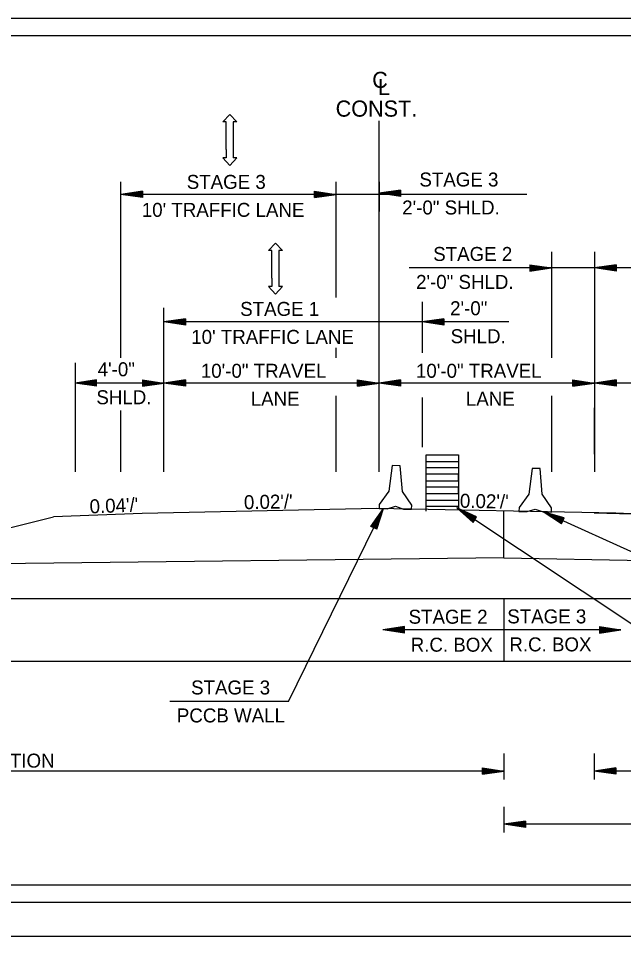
# Model space of a CAD drawing. Extents: x 1368648 to 1927880, y -1037443 to 380209.
# Drawn here: x 1372375 to 1372727, y 378686 to 379220 of the extents above; entities that cross this region are included whole.
import ezdxf

# ---------------------------------------------------------------- set-up
doc = ezdxf.new("R2010")
doc.units = 0
for name, color, linetype in [('CL Construction', 7, 'Continuous'), ('Default', 7, 'Continuous'), ('Dimensions', 7, 'Continuous'), ('Level 1', 7, 'Continuous'), ('R_Border', 7, 'Continuous'), ('R_Dimension', 7, 'Continuous'), ('R_Fin Surface', 7, 'Continuous'), ('R_MOT', 7, 'Continuous'), ('R_No Plot', 7, 'Continuous')]:
    doc.layers.add(name, color=color, linetype=linetype)

msp = doc.modelspace()

# ---------------------------------------------------------------- linework, layer by layer
at = {"layer": 'CL Construction'}
msp.add_line((1372584.51, 378956.16), (1372584.51, 379160.03), dxfattribs=at)
at = {"layer": 'Default'}
for p, q in [((1372611.88, 378965.96), (1372630.63, 378965.96)), ((1372611.88, 378933.35), (1372611.88, 378965.96)), ((1372630.63, 378965.96), (1372630.63, 378933.81)), ((1372611.88, 378962.21), (1372630.63, 378962.21)), ((1372611.88, 378958.46), (1372611.88, 378962.21)), ((1372630.63, 378958.46), (1372611.88, 378958.46)), ((1372630.63, 378954.71), (1372611.88, 378954.71)), ((1372630.63, 378950.96), (1372630.63, 378954.71)), ((1372611.88, 378950.96), (1372630.63, 378950.96)), ((1372630.63, 378947.21), (1372611.88, 378947.21)), ((1372611.88, 378943.46), (1372630.63, 378943.46)), ((1372630.63, 378943.46), (1372630.63, 378947.21)), ((1372611.88, 378939.71), (1372630.63, 378939.71)), ((1372611.88, 378935.96), (1372611.88, 378939.71)), ((1372630.63, 378935.96), (1372611.88, 378935.96)), ((1372656.97, 378906.24), (1372656.97, 378933.3)), ((1372656.97, 378906.24), (1372282.17, 378901.64)), ((1372656.97, 378906.24), (1372949.06, 378900.4)), ((1372205.32, 378882.43), (1372960.45, 378882.49)), ((1372656.97, 378882.47), (1372656.97, 378846.12)), ((1372141.41, 378846.12), (1373024.35, 378846.12))]:
    msp.add_line(p, q, dxfattribs=at)
at = {"layer": 'Dimensions'}
for p, q in [((1372499.82, 379159.39), (1372499.82, 379138.49)), ((1372526.35, 379084.63), (1372526.35, 379063.74))]:
    msp.add_line(p, q, dxfattribs=at)
for points in [[(1372495.76, 379143.37), (1372495.76, 379159.39), (1372493.73, 379159.39), (1372497.79, 379163.84), (1372501.85, 379159.39), (1372499.82, 379159.39)], [(1372495.76, 379143.37), (1372495.76, 379138.49), (1372493.73, 379138.49), (1372497.79, 379134.04), (1372501.85, 379138.49), (1372499.82, 379138.49)], [(1372522.28, 379068.61), (1372522.28, 379084.63), (1372520.25, 379084.63), (1372524.31, 379089.08), (1372528.38, 379084.63), (1372526.35, 379084.63)], [(1372522.28, 379068.61), (1372522.28, 379063.74), (1372520.25, 379063.74), (1372524.31, 379059.29), (1372528.38, 379063.74), (1372526.35, 379063.74)]]:
    msp.add_lwpolyline(points, dxfattribs=at)
at = {"layer": 'Level 1'}
for p, q in [((1372592.1, 378959.71), (1372590.24, 378944.82)), ((1372596.81, 378959.61), (1372592.1, 378959.71)), ((1372598.09, 378944.66), (1372596.81, 378959.61)), ((1372673.31, 378958.11), (1372671.45, 378943.23)), ((1372678.02, 378958.02), (1372673.31, 378958.11)), ((1372679.3, 378943.07), (1372678.02, 378958.02)), ((1372590.24, 378944.82), (1372584.59, 378937.07)), ((1372603.43, 378936.7), (1372598.09, 378944.66)), ((1372671.45, 378943.23), (1372665.8, 378935.48)), ((1372684.64, 378935.11), (1372679.3, 378943.07)), ((1372584.59, 378937.07), (1372584.51, 378934.72)), ((1372584.51, 378934.72), (1372589.22, 378934.63)), ((1372589.22, 378934.63), (1372593.97, 378936.1)), ((1372593.97, 378936.1), (1372598.65, 378934.44)), ((1372598.65, 378934.44), (1372603.36, 378934.35)), ((1372603.36, 378934.35), (1372603.43, 378936.7)), ((1372665.8, 378935.48), (1372665.73, 378933.13)), ((1372665.73, 378933.13), (1372670.44, 378933.03)), ((1372670.44, 378933.03), (1372675.18, 378934.51)), ((1372675.18, 378934.51), (1372679.86, 378932.85)), ((1372679.86, 378932.85), (1372684.57, 378932.76)), ((1372684.57, 378932.76), (1372684.64, 378935.11))]:
    msp.add_line(p, q, dxfattribs=at)
at = {"layer": 'R_Border'}
for p, q in [((1373388.3, 379219.61), (1371807.4, 379219.61)), ((1373388.3, 378705.96), (1371807.4, 378705.96))]:
    msp.add_line(p, q, dxfattribs=at)
at = {"layer": 'R_Dimension'}
for p, q in [((1372434.51, 379022.35), (1372434.51, 379124.6)), ((1372559.51, 379057.43), (1372559.51, 379124.6)), ((1372584.51, 379124.6), (1372584.51, 379107.42)), ((1372447.01, 379119.18), (1372434.51, 379117.31)), ((1372447.01, 379119.18), (1372447.01, 379115.43)), ((1372547.01, 379119.18), (1372559.51, 379117.31)), ((1372547.01, 379115.43), (1372547.01, 379119.18)), ((1372597.01, 379119.82), (1372584.51, 379117.95)), ((1372597.01, 379119.51), (1372586.6, 379117.95)), ((1372597.01, 379119.19), (1372588.75, 379117.95)), ((1372597.01, 379119.82), (1372597.01, 379116.07)), ((1372670.3, 379117.31), (1372434.51, 379117.31)), ((1372447.01, 379115.43), (1372434.51, 379117.31)), ((1372447.01, 379118.87), (1372436.6, 379117.31)), ((1372447.01, 379115.75), (1372436.6, 379117.31)), ((1372447.01, 379118.55), (1372438.75, 379117.31)), ((1372447.01, 379116.06), (1372438.75, 379117.31)), ((1372447.01, 379118.24), (1372440.83, 379117.31)), ((1372447.01, 379116.38), (1372440.83, 379117.31)), ((1372447.01, 379117.91), (1372442.95, 379117.31)), ((1372447.01, 379116.7), (1372442.95, 379117.31)), ((1372447.01, 379117.6), (1372445.04, 379117.31)), ((1372447.01, 379117.01), (1372445.04, 379117.31)), ((1372547.01, 379118.87), (1372557.43, 379117.31)), ((1372547.01, 379118.55), (1372555.28, 379117.31)), ((1372547.01, 379118.24), (1372553.19, 379117.31)), ((1372547.01, 379117.92), (1372551.08, 379117.31)), ((1372547.01, 379117.6), (1372548.99, 379117.31)), ((1372547.01, 379115.43), (1372559.51, 379117.31)), ((1372547.01, 379116.7), (1372551.08, 379117.31)), ((1372547.01, 379116.06), (1372555.28, 379117.31)), ((1372547.01, 379115.75), (1372557.43, 379117.31)), ((1372547.01, 379116.38), (1372553.19, 379117.31)), ((1372547.01, 379117.01), (1372548.99, 379117.31)), ((1372597.01, 379116.07), (1372584.51, 379117.95)), ((1372597.01, 379116.38), (1372586.6, 379117.95)), ((1372597.01, 379116.7), (1372588.75, 379117.95)), ((1372597.01, 379118.88), (1372590.83, 379117.95)), ((1372597.01, 379117.02), (1372590.83, 379117.95)), ((1372597.01, 379118.55), (1372592.95, 379117.95)), ((1372597.01, 379117.33), (1372592.95, 379117.95)), ((1372597.01, 379118.24), (1372595.04, 379117.95)), ((1372597.01, 379117.65), (1372595.04, 379117.95)), ((1372684.57, 379084), (1372684.57, 379022.35)), ((1372709.57, 379084), (1372709.57, 378956.16)), ((1372672.07, 379076.46), (1372684.57, 379074.59)), ((1372672.07, 379076.46), (1372672.07, 379072.71)), ((1372722.13, 379076.45), (1372709.63, 379074.58)), ((1372722.13, 379076.45), (1372722.13, 379072.7)), ((1372847.17, 379074.58), (1372601.97, 379074.58)), ((1372672.07, 379076.15), (1372682.48, 379074.59)), ((1372672.07, 379075.83), (1372680.33, 379074.59)), ((1372672.07, 379075.52), (1372678.25, 379074.59)), ((1372672.07, 379075.19), (1372676.13, 379074.59)), ((1372672.07, 379074.88), (1372674.05, 379074.59)), ((1372672.07, 379072.71), (1372684.57, 379074.59)), ((1372672.07, 379073.98), (1372676.13, 379074.59)), ((1372672.07, 379073.34), (1372680.33, 379074.59)), ((1372672.07, 379073.03), (1372682.48, 379074.59)), ((1372672.07, 379073.66), (1372678.25, 379074.59)), ((1372672.07, 379074.29), (1372674.05, 379074.59)), ((1372722.13, 379072.7), (1372709.63, 379074.58)), ((1372722.13, 379076.14), (1372711.72, 379074.58)), ((1372722.13, 379073.02), (1372711.72, 379074.58)), ((1372722.13, 379075.82), (1372713.87, 379074.58)), ((1372722.13, 379073.34), (1372713.87, 379074.58)), ((1372722.13, 379075.51), (1372715.95, 379074.58)), ((1372722.13, 379073.65), (1372715.95, 379074.58)), ((1372722.13, 379075.19), (1372718.07, 379074.58)), ((1372722.13, 379073.97), (1372718.07, 379074.58)), ((1372722.13, 379074.87), (1372720.15, 379074.58)), ((1372722.13, 379074.29), (1372720.15, 379074.58)), ((1372459.55, 379023.3), (1372459.52, 379051.47)), ((1372609.51, 379054.94), (1372609.51, 379025.27)), ((1372472.04, 379045.05), (1372459.54, 379043.18)), ((1372472.04, 379044.74), (1372461.63, 379043.18)), ((1372472.04, 379044.42), (1372463.78, 379043.18)), ((1372472.04, 379045.05), (1372472.04, 379041.3)), ((1372622.01, 379045.05), (1372609.51, 379043.18)), ((1372622.01, 379044.74), (1372611.6, 379043.18)), ((1372622.01, 379044.42), (1372613.75, 379043.18)), ((1372622.01, 379045.05), (1372622.01, 379041.3)), ((1372584.49, 379043.18), (1372459.54, 379043.18)), ((1372472.04, 379041.3), (1372459.54, 379043.18)), ((1372472.04, 379041.61), (1372461.63, 379043.18)), ((1372472.04, 379041.93), (1372463.78, 379043.18)), ((1372472.04, 379044.11), (1372465.86, 379043.18)), ((1372472.04, 379042.24), (1372465.86, 379043.18)), ((1372472.04, 379043.78), (1372467.98, 379043.18)), ((1372472.04, 379042.56), (1372467.98, 379043.18)), ((1372472.04, 379043.47), (1372470.06, 379043.18)), ((1372472.04, 379042.88), (1372470.06, 379043.18)), ((1372659.94, 379043.18), (1372584.51, 379043.18)), ((1372622.01, 379041.3), (1372609.51, 379043.18)), ((1372622.01, 379041.61), (1372611.6, 379043.18)), ((1372622.01, 379041.93), (1372613.75, 379043.18)), ((1372622.01, 379044.11), (1372615.83, 379043.18)), ((1372622.01, 379042.24), (1372615.83, 379043.18)), ((1372622.01, 379043.78), (1372617.95, 379043.18)), ((1372622.01, 379042.56), (1372617.95, 379043.18)), ((1372622.01, 379043.47), (1372620.04, 379043.18)), ((1372622.01, 379042.88), (1372620.04, 379043.18)), ((1372459.55, 378997.03), (1372459.55, 379023.3)), ((1372559.51, 379022.35), (1372559.51, 379028.18)), ((1372407.96, 379019.44), (1372407.96, 378966.59)), ((1372420.46, 379009.56), (1372407.96, 379007.69)), ((1372459.54, 379007.69), (1372407.96, 379007.69)), ((1372420.46, 379005.81), (1372407.96, 379007.69)), ((1372420.46, 379009.25), (1372410.05, 379007.69)), ((1372420.46, 379006.13), (1372410.05, 379007.69)), ((1372420.46, 379008.93), (1372412.2, 379007.69)), ((1372420.46, 379006.45), (1372412.2, 379007.69)), ((1372420.46, 379008.62), (1372414.28, 379007.69)), ((1372420.46, 379006.76), (1372414.28, 379007.69)), ((1372420.46, 379008.3), (1372416.4, 379007.69)), ((1372420.46, 379007.08), (1372416.4, 379007.69)), ((1372420.46, 379007.98), (1372418.49, 379007.69)), ((1372420.46, 379007.4), (1372418.49, 379007.69)), ((1372420.46, 379005.81), (1372420.46, 379009.56)), ((1372447.04, 379009.56), (1372459.54, 379007.69)), ((1372447.04, 379009.56), (1372447.04, 379005.81)), ((1372447.04, 379009.25), (1372457.45, 379007.69)), ((1372447.04, 379008.93), (1372455.3, 379007.69)), ((1372447.04, 379008.62), (1372453.22, 379007.69)), ((1372447.04, 379008.3), (1372451.1, 379007.69)), ((1372447.04, 379007.98), (1372449.01, 379007.69)), ((1372447.04, 379005.81), (1372459.54, 379007.69)), ((1372447.04, 379007.08), (1372451.1, 379007.69)), ((1372447.04, 379006.45), (1372455.3, 379007.69)), ((1372447.04, 379006.13), (1372457.45, 379007.69)), ((1372447.04, 379006.76), (1372453.22, 379007.69)), ((1372447.04, 379007.4), (1372449.01, 379007.69)), ((1372472.04, 379009.56), (1372459.54, 379007.69)), ((1372584.49, 379007.69), (1372459.54, 379007.69)), ((1372472.04, 379005.81), (1372459.54, 379007.69)), ((1372472.04, 379009.25), (1372461.63, 379007.69)), ((1372472.04, 379006.13), (1372461.63, 379007.69)), ((1372472.04, 379008.93), (1372463.78, 379007.69)), ((1372472.04, 379006.45), (1372463.78, 379007.69)), ((1372472.04, 379008.62), (1372465.86, 379007.69)), ((1372472.04, 379006.76), (1372465.86, 379007.69)), ((1372472.04, 379008.3), (1372467.98, 379007.69)), ((1372472.04, 379007.08), (1372467.98, 379007.69)), ((1372472.04, 379007.98), (1372470.06, 379007.69)), ((1372472.04, 379007.4), (1372470.06, 379007.69)), ((1372472.04, 379009.56), (1372472.04, 379005.81)), ((1372572.05, 379009.57), (1372584.55, 379007.7)), ((1372572.05, 379005.82), (1372572.05, 379009.57)), ((1372572.05, 379009.26), (1372582.46, 379007.7)), ((1372572.05, 379008.94), (1372580.31, 379007.7)), ((1372572.05, 379008.63), (1372578.23, 379007.7)), ((1372572.05, 379008.31), (1372576.11, 379007.7)), ((1372572.05, 379007.99), (1372574.02, 379007.7)), ((1372572.05, 379005.82), (1372584.55, 379007.7)), ((1372572.05, 379007.09), (1372576.11, 379007.7)), ((1372572.05, 379006.45), (1372580.31, 379007.7)), ((1372572.05, 379006.14), (1372582.46, 379007.7)), ((1372572.05, 379006.77), (1372578.23, 379007.7)), ((1372572.05, 379007.4), (1372574.02, 379007.7)), ((1372596.99, 379009.56), (1372584.49, 379007.69)), ((1372709.5, 379007.69), (1372584.49, 379007.69)), ((1372596.99, 379005.81), (1372584.49, 379007.69)), ((1372596.99, 379009.25), (1372586.58, 379007.69)), ((1372596.99, 379006.13), (1372586.58, 379007.69)), ((1372596.99, 379008.93), (1372588.73, 379007.69)), ((1372596.99, 379006.45), (1372588.73, 379007.69)), ((1372596.99, 379008.62), (1372590.81, 379007.69)), ((1372596.99, 379006.76), (1372590.81, 379007.69)), ((1372596.99, 379008.3), (1372592.93, 379007.69)), ((1372596.99, 379007.08), (1372592.93, 379007.69)), ((1372596.99, 379007.98), (1372595.01, 379007.69)), ((1372596.99, 379007.4), (1372595.01, 379007.69)), ((1372596.99, 379009.56), (1372596.99, 379005.81)), ((1372697, 379009.56), (1372709.5, 379007.69)), ((1372697, 379005.81), (1372697, 379009.56)), ((1372697, 379009.25), (1372707.41, 379007.69)), ((1372697, 379008.93), (1372705.26, 379007.69)), ((1372697, 379008.62), (1372703.18, 379007.69)), ((1372697, 379008.3), (1372701.06, 379007.69)), ((1372697, 379007.98), (1372698.98, 379007.69)), ((1372697, 379005.81), (1372709.5, 379007.69)), ((1372697, 379007.08), (1372701.06, 379007.69)), ((1372697, 379006.45), (1372705.26, 379007.69)), ((1372697, 379006.13), (1372707.41, 379007.69)), ((1372697, 379006.76), (1372703.18, 379007.69)), ((1372697, 379007.4), (1372698.98, 379007.69)), ((1372722.13, 379009.55), (1372709.63, 379007.68)), ((1372722.13, 379005.8), (1372709.63, 379007.68)), ((1372924.68, 379007.68), (1372709.63, 379007.68)), ((1372722.13, 379009.24), (1372711.72, 379007.68)), ((1372722.13, 379006.12), (1372711.72, 379007.68)), ((1372722.13, 379008.92), (1372713.87, 379007.68)), ((1372722.13, 379006.43), (1372713.87, 379007.68)), ((1372722.13, 379008.61), (1372715.95, 379007.68)), ((1372722.13, 379006.75), (1372715.95, 379007.68)), ((1372722.13, 379008.28), (1372718.07, 379007.68)), ((1372722.13, 379007.07), (1372718.07, 379007.68)), ((1372722.13, 379007.97), (1372720.15, 379007.68)), ((1372722.13, 379007.38), (1372720.15, 379007.68)), ((1372722.13, 379009.55), (1372722.13, 379005.8)), ((1372459.55, 378975.88), (1372459.53, 378997.03)), ((1372559.51, 378956.16), (1372559.51, 379000.23)), ((1372609.51, 378999.26), (1372609.51, 378970.38)), ((1372684.57, 379000.23), (1372684.57, 378956.16)), ((1372434.51, 378956.16), (1372434.51, 378991.71)), ((1372709.57, 378966.34), (1372709.57, 378993.21)), ((1372459.55, 378956.16), (1372459.55, 378975.88)), ((1372407.96, 378966.59), (1372407.96, 378956.16)), ((1372531.93, 378822.67), (1372586.95, 378934.83)), ((1372579.76, 378924.44), (1372586.97, 378934.82)), ((1372580.04, 378924.3), (1372586.05, 378932.95)), ((1372582.85, 378922.92), (1372586.05, 378932.95)), ((1372583.13, 378922.78), (1372586.97, 378934.82)), ((1372798.39, 378822.67), (1372629.73, 378935.27)), ((1372639.08, 378926.77), (1372629.73, 378935.27)), ((1372641.16, 378929.89), (1372629.73, 378935.27)), ((1372639.25, 378927.03), (1372631.46, 378934.11)), ((1372640.99, 378929.63), (1372631.46, 378934.11)), ((1372640.81, 378929.37), (1372633.25, 378932.92)), ((1372639.43, 378927.3), (1372633.25, 378932.92)), ((1372922.45, 378822.67), (1372679.86, 378932.85)), ((1372690.47, 378925.97), (1372679.86, 378932.85)), ((1372692.02, 378929.39), (1372679.86, 378932.85)), ((1372580.33, 378924.16), (1372585.1, 378931.02)), ((1372580.61, 378924.03), (1372584.18, 378929.16)), ((1372580.9, 378923.88), (1372583.24, 378927.26)), ((1372581.99, 378923.35), (1372583.24, 378927.26)), ((1372582.28, 378923.2), (1372584.18, 378929.16)), ((1372582.56, 378923.06), (1372585.1, 378931.02)), ((1372639.61, 378927.56), (1372634.98, 378931.77)), ((1372640.64, 378929.11), (1372634.98, 378931.77)), ((1372640.46, 378928.84), (1372636.74, 378930.59)), ((1372639.79, 378927.83), (1372636.74, 378930.59)), ((1372640.29, 378928.58), (1372638.48, 378929.43)), ((1372639.96, 378928.09), (1372638.48, 378929.43)), ((1372639.08, 378926.77), (1372641.16, 378929.89)), ((1372690.59, 378926.26), (1372681.76, 378931.99)), ((1372691.89, 378929.1), (1372681.76, 378931.99)), ((1372691.76, 378928.81), (1372683.72, 378931.1)), ((1372690.73, 378926.55), (1372683.72, 378931.1)), ((1372690.86, 378926.83), (1372685.61, 378930.24)), ((1372691.63, 378928.53), (1372685.61, 378930.24)), ((1372691.49, 378928.24), (1372687.54, 378929.36)), ((1372690.99, 378927.13), (1372687.54, 378929.36)), ((1372691.36, 378927.95), (1372689.44, 378928.5)), ((1372691.12, 378927.41), (1372689.44, 378928.5)), ((1372690.47, 378925.97), (1372692.02, 378929.39)), ((1372583.13, 378922.78), (1372579.76, 378924.44)), ((1372581.18, 378923.74), (1372582.32, 378925.38)), ((1372581.71, 378923.48), (1372582.32, 378925.38)), ((1372599.16, 378866.17), (1372586.66, 378864.3)), ((1372724.92, 378864.3), (1372586.66, 378864.3)), ((1372599.16, 378862.42), (1372586.66, 378864.3)), ((1372599.16, 378865.86), (1372588.74, 378864.3)), ((1372599.16, 378862.73), (1372588.74, 378864.3)), ((1372599.16, 378865.54), (1372590.89, 378864.3)), ((1372599.16, 378863.05), (1372590.89, 378864.3)), ((1372599.16, 378865.23), (1372592.98, 378864.3)), ((1372599.16, 378863.37), (1372592.98, 378864.3)), ((1372599.16, 378864.91), (1372595.09, 378864.3)), ((1372599.16, 378863.69), (1372595.09, 378864.3)), ((1372599.16, 378864.59), (1372597.18, 378864.3)), ((1372599.16, 378864), (1372597.18, 378864.3)), ((1372599.16, 378862.42), (1372599.16, 378866.17)), ((1372712.42, 378866.17), (1372724.92, 378864.3)), ((1372712.42, 378866.17), (1372712.42, 378862.42)), ((1372712.42, 378865.86), (1372722.83, 378864.3)), ((1372712.42, 378865.54), (1372720.68, 378864.3)), ((1372712.42, 378865.23), (1372718.6, 378864.3)), ((1372712.42, 378864.9), (1372716.48, 378864.3)), ((1372712.42, 378864.59), (1372714.4, 378864.3)), ((1372712.42, 378862.42), (1372724.92, 378864.3)), ((1372712.42, 378863.68), (1372716.48, 378864.3)), ((1372712.42, 378863.05), (1372720.68, 378864.3)), ((1372712.42, 378862.73), (1372722.83, 378864.3)), ((1372712.42, 378863.37), (1372718.6, 378864.3)), ((1372712.42, 378864), (1372714.4, 378864.3)), ((1372531.93, 378822.67), (1372462.88, 378822.67)), ((1372656.97, 378792.37), (1372656.97, 378779.9)), ((1372709.49, 378792.37), (1372709.49, 378779.9)), ((1372644.47, 378784.12), (1372656.97, 378782.24)), ((1372644.47, 378780.37), (1372644.47, 378784.12)), ((1372644.47, 378783.8), (1372654.88, 378782.24)), ((1372644.47, 378783.49), (1372652.73, 378782.24)), ((1372644.47, 378783.17), (1372650.65, 378782.24)), ((1372721.99, 378784.12), (1372709.49, 378782.24)), ((1372721.99, 378783.8), (1372711.58, 378782.24)), ((1372721.99, 378783.49), (1372713.73, 378782.24)), ((1372721.99, 378783.17), (1372715.81, 378782.24)), ((1372721.99, 378784.12), (1372721.99, 378780.37)), ((1372656.97, 378782.24), (1372080.75, 378782.24)), ((1372644.47, 378782.85), (1372648.53, 378782.24)), ((1372644.47, 378782.54), (1372646.45, 378782.24)), ((1372644.47, 378780.37), (1372656.97, 378782.24)), ((1372644.47, 378781.64), (1372648.53, 378782.24)), ((1372644.47, 378781), (1372652.73, 378782.24)), ((1372644.47, 378780.68), (1372654.88, 378782.24)), ((1372644.47, 378781.31), (1372650.65, 378782.24)), ((1372644.47, 378781.95), (1372646.45, 378782.24)), ((1372656.97, 378779.9), (1372656.97, 378777.44)), ((1373078.23, 378782.24), (1372709.49, 378782.24)), ((1372721.99, 378780.37), (1372709.49, 378782.24)), ((1372709.49, 378779.9), (1372709.49, 378777.44)), ((1372721.99, 378780.68), (1372711.58, 378782.24)), ((1372721.99, 378781), (1372713.73, 378782.24)), ((1372721.99, 378781.31), (1372715.81, 378782.24)), ((1372721.99, 378782.85), (1372717.93, 378782.24)), ((1372721.99, 378781.63), (1372717.93, 378782.24)), ((1372721.99, 378782.54), (1372720.01, 378782.24)), ((1372721.99, 378781.95), (1372720.01, 378782.24)), ((1372656.97, 378761.43), (1372656.97, 378748.96)), ((1372669.47, 378753.18), (1372656.97, 378751.3)), ((1373130.18, 378751.3), (1372656.97, 378751.3)), ((1372669.47, 378749.43), (1372656.97, 378751.3)), ((1372669.47, 378752.86), (1372659.06, 378751.3)), ((1372669.47, 378749.74), (1372659.06, 378751.3)), ((1372669.47, 378752.54), (1372661.21, 378751.3)), ((1372669.47, 378750.06), (1372661.21, 378751.3)), ((1372669.47, 378752.23), (1372663.29, 378751.3)), ((1372669.47, 378750.37), (1372663.29, 378751.3)), ((1372669.47, 378751.91), (1372665.41, 378751.3)), ((1372669.47, 378750.69), (1372665.41, 378751.3)), ((1372669.47, 378751.59), (1372667.5, 378751.3)), ((1372669.47, 378751.01), (1372667.5, 378751.3)), ((1372669.47, 378753.18), (1372669.47, 378749.43)), ((1372656.97, 378748.96), (1372656.97, 378746.5))]:
    msp.add_line(p, q, dxfattribs=at)
at = {"layer": 'R_Fin Surface'}
msp.add_line((1372205.32, 378882.43), (1372395.44, 378929.96), dxfattribs=at)
at = {"layer": 'R_MOT'}
msp.add_line((1372709.49, 378932.27), (1372874.26, 378928.07), dxfattribs=at)
msp.add_lwpolyline([(1372772.01, 378930.02), (1372721.99, 378932.02), (1372583.12, 378934.75), (1372446.87, 378931.97), (1372395.44, 378929.96)], dxfattribs=at)
at = {"layer": 'R_No Plot'}
for points in [[(1371745.37, 379752.73), (1373412.07, 379752.73), (1373412.07, 378686.04), (1371745.37, 378686.04)], [(1371817.4, 379723.26), (1373065.1, 379723.26), (1373065.1, 379673.86), (1373152.8, 379673.86), (1373273.3, 379673.86), (1373273.3, 379562.19), (1373378.3, 379562.19), (1373378.3, 378715.96), (1371817.4, 378715.96)], [(1371817.4, 379209.61), (1373378.3, 379209.61), (1373378.3, 378715.96), (1371817.4, 378715.96)]]:
    msp.add_lwpolyline(points, close=True, dxfattribs=at)

# ---------------------------------------------------------------- texts
at = {"layer": 'CL Construction'}
for s, height, p in [('C', 9.37, (1372580.5, 379179.18)), ('L', 9.37, (1372583.8, 379175.06)), ('CONST.', 9.375, (1372559.27, 379162.49))]:
    msp.add_text(s, height=height, dxfattribs=at).set_placement(p)
at = {"layer": 'Default'}
msp.add_text("0.04'/'", height=8.125, rotation=2.2906, dxfattribs=at).set_placement((1372416.53, 378931.91))
at = {"layer": 'R_Dimension'}
for s, p in [('STAGE 3 ', (1372607.9, 379121.9)), ('STAGE 3', (1372472.78, 379120.52)), ('2\'-0" SHLD.', (1372597.92, 379105.65)), ("10' TRAFFIC LANE", (1372446.68, 379104.27)), ('STAGE 2', (1372615.94, 379078.65)), ('2\'-0" SHLD.', (1372605.96, 379062.4)), (' 2\'-0"', (1372622.72, 379047.11)), ('STAGE 1', (1372503.81, 379046.73)), ('SHLD.', (1372626.05, 379030.86)), ("10' TRAFFIC LANE", (1372475.4, 379030.48)), ('4\'-0"', (1372421.04, 379011.64)), ('10\'-0" TRAVEL', (1372480.96, 379010.77)), ('10\'-0" TRAVEL', (1372605.92, 379010.77)), ('SHLD.', (1372420.3, 378995.39)), ('LANE', (1372509.94, 378994.52)), ('LANE', (1372634.9, 378994.52)), ('STAGE 2', (1372601.63, 378867.86)), ('STAGE 3', (1372658.94, 378868.05)), ('R.C. BOX', (1372602.85, 378851.61)), ('R.C. BOX', (1372660.15, 378851.8)), ('STAGE 3', (1372475.3, 378826.75)), ('PCCB WALL', (1372467.05, 378810.5)), ('STAGE 2 CONSTRUCTION', (1372259.6, 378784.24))]:
    msp.add_text(s, height=8.125, dxfattribs=at).set_placement(p)
for rotation, p in [(1.1458, (1372506.07, 378934.37)), (358.8542, (1372631.36, 378935.28))]:
    msp.add_text("0.02'/'", height=8.125, rotation=rotation, dxfattribs=at).set_placement(p)

doc.saveas('drawing.dxf')
